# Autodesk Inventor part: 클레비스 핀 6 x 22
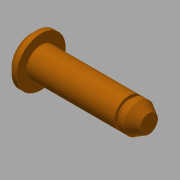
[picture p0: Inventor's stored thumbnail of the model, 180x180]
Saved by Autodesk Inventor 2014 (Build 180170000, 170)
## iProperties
IsCustomPart: 1
Created: 2017-08
Part Number: 클레비스 핀 6 x 22
Material: 강철
Description: 머리가 있는 클레비스 핀
Document SubType Name: Modeling
Standard: ISO 2341
Designer: mduedu
Standard Revision: Second edition 1986-11-01
Standards Organization: ISO
Language: ko-KR
Size Designation: B - 6 x 24
Categories: <MemberInstance><Categories><Category DisplayName="조임쇠" InternalName="e4da775c-781d-43d5-af7c-5136215cf5a6" Mnemonic="FSTN"><Category DisplayName="핀" InternalNa
Density: 7.85 g/cm^3
Appearance: 주황색
Author: mduedu
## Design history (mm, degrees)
sketch "스케치1"
  geometry: L1 (-2, 0)-(-2, 5); L2 (-2, 5)-(0, 5); L3 (0, 5)-(0, 3); L4 (0, 3)-(22, 3); L5 (22, 3)-(22, 0); L6 (-2, 0)-(22, 0); L7 (-7, 0)-(28, 0) reference; L8 (0, -1.96)-(0, 6.16) reference; C1 r 0.8 at (18.8, 0)
  constraints: 12 end point, 3 parallel, 2 collinear, 2 perpendicular, 1 centre point, 1 point on line, 1 vertical
  dimensions: "d0" = 6 diameter of L4 L6 (= NND); "d1" = 10 diameter of L2 L6 (= KOD); "d2" = 2 distance of L1.end L2.end (= KOH); "d3" = 22 distance of L3.end L4.end (= NLG); "d5" = 3.2 distance from line of L5 C1.centre (= DIST); "d6" = 1.6 diameter of C1 (= BOR)
revolve "본체" stored, may be unused: angle "d4" = 90 deg
workplane "Work Plane1"
node "작업 평면4"
sketch "스케치2"
  geometry: C1 r 3 at (0, 0) reference; C2 r 2.425 at (0, 0); 1 further point
  constraints: 1 centre point, 1 coincident
  dimensions: "d33" = 4.85 diameter of C2
extrude "돌출2" cut sketch "스케치2" distance "d34" = 0.7; taper "d35" = 0 deg
body "Solid1"
chamfer "모따기1" distance "d9" = 1 (= PHH2); stored, may be unused: angle "d10" = 45 deg (= FAWI2), second distance "d16" = 1 (= PHH2)
chamfer "모따기2" distance "d11" = 2 (= PHH1); stored, may be unused: angle "d12" = 30 deg (= FAWI1), second distance "d17" = 2 (= PHH1)
other parameters: "PHH1" = 2 [user parameter; used in 2 equation terms], "PHH2" = 1 [user parameter; used in 2 equation terms], "KOD" = 10 [user parameter; used in 1 equation term], "KOH" = 2 [user parameter; used in 1 equation term], "NND" = 6 [user parameter; used in 1 equation term], "FAWI1" = 30 deg [user parameter; used in 1 equation term], "FAWI2" = 45 deg [user parameter; used in 1 equation term], "DIST" = 3.2 [user parameter; used in 1 equation term], "BOR" = 1.6 [user parameter; used in 1 equation term], "NLG" = 22 [user parameter; used in 1 equation term], "d13" = 0, "d14" = 0, "d30" = 0, "d32" = 18
